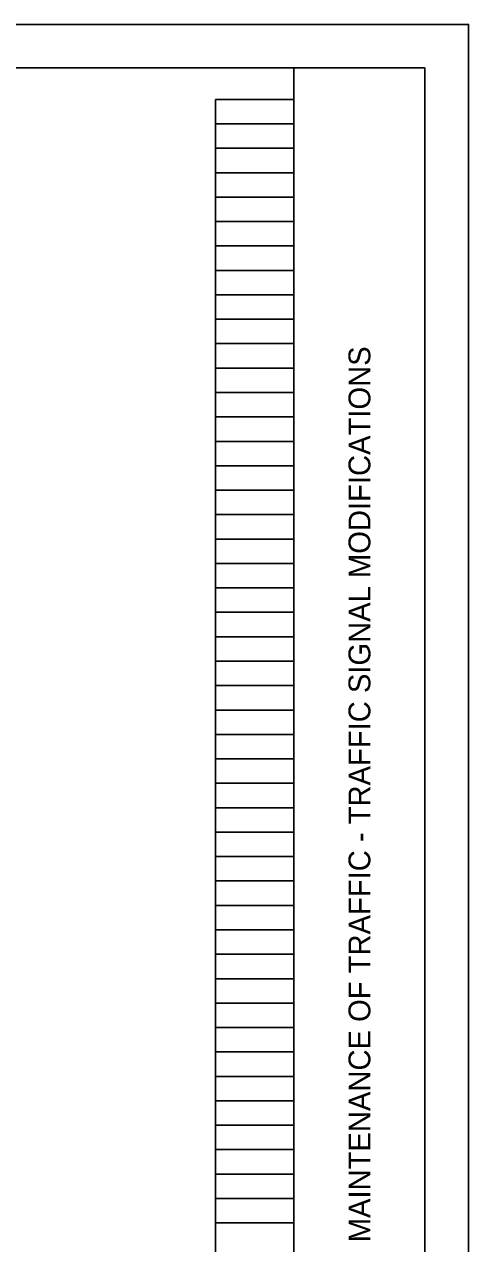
# Model space of a CAD drawing. Extents: x 0 to 40.3, y -1.2 to 22.
# Drawn here: x 28.91 to 34, y 8.02 to 22 of the extents above; entities that cross this region are included whole.
import ezdxf

# ---------------------------------------------------------------- set-up
doc = ezdxf.new("R2010")
doc.units = 0
for name, color, linetype in [('SH_Border', 7, 'Continuous'), ('SH_Cut_Line', 7, 'Continuous'), ('SH_Data', 7, 'Continuous')]:
    doc.layers.add(name, color=color, linetype=linetype)

msp = doc.modelspace()

# ---------------------------------------------------------------- linework, layer by layer
at = {"layer": 'SH_Border'}
msp.add_line((32, 0.5), (32, 21.5), dxfattribs=at)
msp.add_lwpolyline([(1.5, 21.5), (33.5, 21.5), (33.5, 0.5), (1.5, 0.5)], close=True, dxfattribs=at)
at = {"layer": 'SH_Cut_Line'}
msp.add_lwpolyline([(0, 0), (34, 0), (34, 22), (0, 22)], close=True, dxfattribs=at)
at = {"layer": 'SH_Data'}
for p, q in [((31.1, 0.98), (31.1, 21.14)), ((31.1, 21.14), (32, 21.14)), ((32, 0.98), (32, 21.14)), ((31.1, 20.86), (32, 20.86)), ((31.1, 20.58), (32, 20.58)), ((31.1, 20.3), (32, 20.3)), ((31.1, 20.02), (32, 20.02)), ((31.1, 19.74), (32, 19.74)), ((31.1, 19.46), (32, 19.46)), ((31.1, 19.18), (32, 19.18)), ((31.1, 18.9), (32, 18.9)), ((31.1, 18.62), (32, 18.62)), ((31.1, 18.34), (32, 18.34)), ((31.1, 18.06), (32, 18.06)), ((31.1, 17.78), (32, 17.78)), ((31.1, 17.5), (32, 17.5)), ((31.1, 17.22), (32, 17.22)), ((31.1, 16.94), (32, 16.94)), ((31.1, 16.66), (32, 16.66)), ((31.1, 16.38), (32, 16.38)), ((31.1, 16.1), (32, 16.1)), ((31.1, 15.82), (32, 15.82)), ((31.1, 15.54), (32, 15.54)), ((31.1, 15.26), (32, 15.26)), ((31.1, 14.98), (32, 14.98)), ((31.1, 14.7), (32, 14.7)), ((31.1, 14.42), (32, 14.42)), ((31.1, 14.14), (32, 14.14)), ((31.1, 13.86), (32, 13.86)), ((31.1, 13.58), (32, 13.58)), ((31.1, 13.3), (32, 13.3)), ((31.1, 13.02), (32, 13.02)), ((31.1, 12.74), (32, 12.74)), ((31.1, 12.46), (32, 12.46)), ((31.1, 12.18), (32, 12.18)), ((31.1, 11.9), (32, 11.9)), ((31.1, 11.62), (32, 11.62)), ((31.1, 11.34), (32, 11.34)), ((31.1, 11.06), (32, 11.06)), ((31.1, 10.78), (32, 10.78)), ((31.1, 10.5), (32, 10.5)), ((31.1, 10.22), (32, 10.22)), ((31.1, 9.94), (32, 9.94)), ((31.1, 9.66), (32, 9.66)), ((31.1, 9.38), (32, 9.38)), ((31.1, 9.1), (32, 9.1)), ((31.1, 8.82), (32, 8.82)), ((31.1, 8.54), (32, 8.54)), ((31.1, 8.26), (32, 8.26))]:
    msp.add_line(p, q, dxfattribs=at)

# ---------------------------------------------------------------- texts
msp.add_text('MAINTENANCE OF TRAFFIC - TRAFFIC SIGNAL MODIFICATIONS', height=0.25, rotation=90, dxfattribs=at).set_placement((32.875, 8.038))

doc.saveas('drawing.dxf')
